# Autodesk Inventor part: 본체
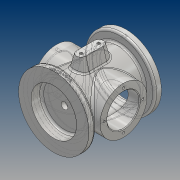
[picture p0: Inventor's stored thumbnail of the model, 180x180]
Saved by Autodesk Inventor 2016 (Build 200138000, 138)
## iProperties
Created: 2018-02
Part Number: 본체
Material: 알루미늄 6061
Document SubType Name: Modeling
Designer: Administrator
Mass: 769.081 g
Surface Area: 821.861 cm^2
Volume: 284.845 cm^3
Density: 2.7 g/cm^3
Appearance: 알루미늄 - 평지
Author: Administrator
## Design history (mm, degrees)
sketch "스케치1"
  geometry: L1 (0, 0)-(0, 108); L2 (0, 108)-(-52.5, 108); L3 (-52.5, 108)-(-52.5, 98); L4 (-52.5, 98)-(-38, 98); L5 (-38, 98)-(-38, 10); L6 (-38, 10)-(-52.5, 10); L7 (-52.5, 10)-(-52.5, 0); L8 (-52.5, 0)-(0, 0)
  constraints: 16 end point, 6 perpendicular, 2 point on line, 1 vertical
  dimensions: "d0" = 105 diameter of L3 L1; "d2" = 76 diameter of L5 L1; "d3" = 10 distance between parallel lines of L6 L8; "d4" = 10 distance between parallel lines of L2 L4; "d5" = 108 distance between parallel lines of L8 L2
revolve "회전1" sketch "스케치1" stored, may be unused: angle "d6" = 90 deg
sketch "스케치2"
  geometry: L1 (-50, 54)-(-50, 89); L2 (-50, 89)-(50, 89); L3 (50, 89)-(50, 54); L4 (50, 54)-(-50, 54); L5 (52.5, 0)-(-52.5, 0) reference; 1 further point
  constraints: 8 end point, 3 perpendicular, 1 vertical
  dimensions: "d7" = 54 distance from line of L5 L1.start; "d8" = 70 diameter of L2 L4; "d9" = 50 distance from line of L1 point (0, 0); "d10" = 100 distance between parallel lines of L3 L1
revolve "회전2" sketch "스케치2" stored, may be unused: angle "d11" = 90 deg
node "작업 평면1"
sketch "스케치3"
  geometry: L1 (0, 67)-(0, 41); L2 (-7, 67)-(-7, 41); L3 (7, 41)-(7, 67); L4 (52.5, 0)-(-52.5, 0) reference; A1 r 7 centre (0, 67) between (7, 67) and (-7, 67); A2 r 7 centre (0, 41) between (-7, 41) and (7, 41); 2 further points
  constraints: 8 end point, 4 point on circle, 4 tangent, 2 centre point, 1 midpoint, 1 parallel, 1 vertical, 1 vertical alignment
  dimensions: "d13" = 54 distance from line of L4 point (0, 54); "d14" = 14 distance between parallel lines of L3 L2; "d15" = 40 dimension on A2 A1
extrude "돌출1" join sketch "스케치3" stored distance "d16" = 10; taper "d17" = 15 deg
hole "구멍1" diameter "d20" = 4.134; stored, may be unused: countersink angle "d24" = 90 deg, drill point angle "d26" = 118 deg; dims "d18" = 10, "d19" = 10, "d21" = 6, "d22" = 4, "d23" = 2, "d25" = 8
hole "구멍2" diameter "d29" = 4.134; stored, may be unused: countersink angle "d33" = 90 deg, drill point angle "d35" = 118 deg; dims "d27" = 10, "d28" = 10, "d30" = 6, "d31" = 4, "d32" = 2, "d34" = 8
sketch "스케치4"
  geometry: L1 (108, -52.5)-(108, 52.5) reference; L2 (108, -37)-(101, -37); L3 (101, -37)-(101, -33); L4 (101, -33)-(25, -33); L5 (22, -30)-(22, -5); L6 (22, -5)-(16, -5); L7 (16, -5)-(16, -31); L8 (13, -34)-(0, -34); L9 (0, -52.5)-(0, 52.5) reference; L10 (108, -37)-(108, 0); L11 (0, 0)-(108, 0); L12 (98, -52.5)-(108, -52.5) reference; L13 (0, -34)-(0, 0); A1 r 3 centre (25, -30) between (22, -30) and (25, -33); A2 r 3 centre (13, -31) between (13, -34) and (16, -31); 1 further point
  constraints: 20 end point, 7 perpendicular, 4 point on circle, 4 tangent, 2 centre point, 2 midpoint, 1 collinear, 1 equal radius, 1 horizontal, 1 point on line
  dimensions: "d36" = 74 diameter of L2 L11; "d37" = 7 distance between parallel lines of L1 L3; "d38" = 66 diameter of L4 L11; "d39" = 79 distance between parallel lines of L3 L5; "d40" = 10 diameter of L6 L11; "d41" = 68 diameter of L8 L11; "d42" = 16 distance between parallel lines of L9 L7; "d43" = 3 radius of A1
revolve "회전3" sketch "스케치4" stored, may be unused: angle "d44" = 90 deg
sketch "스케치5"
  geometry: L1 (-50, 19)-(-50, 89) reference; L2 (-50, 54)-(-50, 78); L3 (-50, 78)-(50, 78); L4 (50, 19)-(50, 89) reference; L5 (-50, 54)-(50, 54); L6 (50, 78)-(50, 54); 1 further point
  constraints: 8 end point, 2 midpoint, 2 point on line, 1 collinear, 1 perpendicular
  dimensions: "d45" = 48 diameter of L3 L5
revolve "회전4" sketch "스케치5" stored, may be unused: angle "d46" = 90 deg
sketch "스케치6" dims "d47" = 58
  geometry: C1 r 24 at (0, 0) reference; C2 r 35 at (0, 0) reference; 3 further points
  constraints: 2 vertical alignment, 1 coincident, 2 other
hole "구멍3" sketch "스케치6" at (0, 29) diameter "d48" = 3.242; stored, may be unused: countersink angle "d52" = 90 deg, drill point angle "d54" = 118 deg; dims "d49" = 4, "d50" = 4, "d51" = 2, "d53" = 6
node "작업축1"
sketch "스케치7" dims "d58" = 90
  geometry: C1 r 5 at (0, 0) reference; 2 further points
  constraints: 2 vertical alignment, 1 coincident, 2 other
hole "구멍4" sketch "스케치7" at (0, 45) diameter "d59" = 3.242; stored, may be unused: countersink angle "d63" = 90 deg, drill point angle "d65" = 118 deg; dims "d60" = 4, "d61" = 4, "d62" = 2, "d64" = 6
fillet "모깎기1" dims "d69" = 3
chamfer "모따기1" distance "d70" = 1; stored, may be unused: second distance "d71" = 2, angle "d72" = 45 deg
sketch "스케치8"
  geometry: C1 r 49.5 at (0, 0) reference; C2 r 43 at (0, 0)
  constraints: 1 centre point, 1 coincident, 1 other
  dimensions: "d73" = 86 diameter of C2
feature "엠보싱1" sketch "스케치8" dims "d0" = 105, "d2" = 76, "d3" = 10, "d4" = 10, "d5" = 108, "d74" = 0.5, "d75" = 0
node "솔리드1"
pattern_circular "원형 패턴1" dims angle "d56" = 360 deg
mirror "대칭1"
pattern_circular "원형 패턴2" dims angle "d67" = 360 deg
other parameters: "d12" = 55
